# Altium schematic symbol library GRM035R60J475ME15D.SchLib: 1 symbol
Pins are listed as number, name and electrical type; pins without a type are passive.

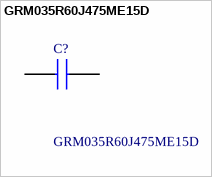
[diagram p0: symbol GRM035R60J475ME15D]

## GRM035R60J475ME15D
designator C?
Multilayer Ceramic Capacitors MLCC - SMD/SMT 0201 4.7uF 6.3volts *Derate Voltage/Temp; Manufacturer_Name: Murata Electronics; Geometry.Height: 0.55mm
footprint CAPC0603X55N
pins: 1, 2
